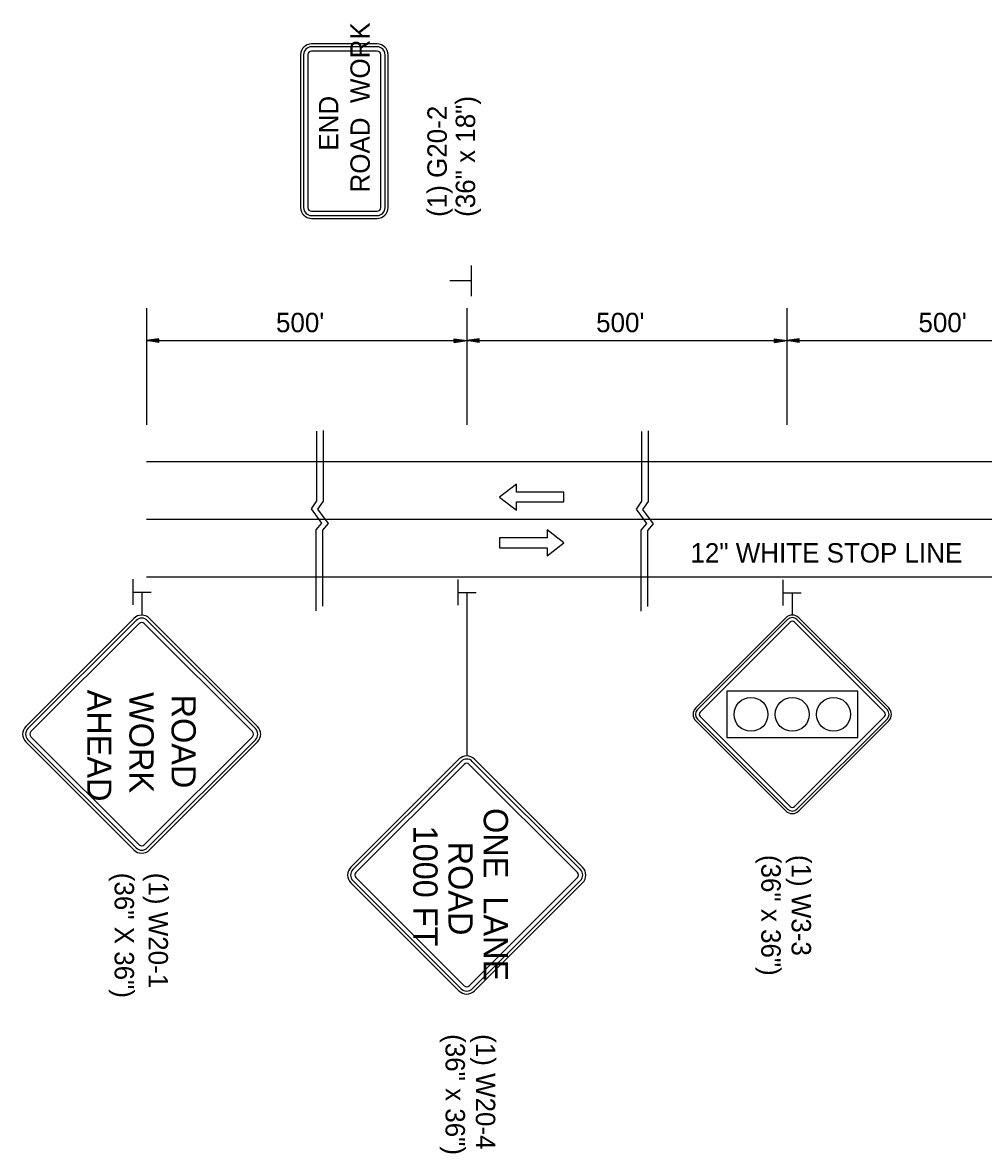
# Model space of a CAD drawing. Extents: x 1926586 to 1930787, y 596452 to 599566.
# Drawn here: x 1927871.2 to 1928168, y 599216.2 to 599565.7 of the extents above; entities that cross this region are included whole.
import ezdxf

# ---------------------------------------------------------------- set-up
doc = ezdxf.new("R2010")
doc.units = 0
for name, color, linetype in [('Default', 7, 'Continuous'), ('P_TC_Signs_Permanent', 7, 'Continuous'), ('P_TC_Signs_Temporary', 7, 'Continuous'), ('R_Border', 7, 'Continuous'), ('R_Striping', 7, 'Continuous')]:
    doc.layers.add(name, color=color, linetype=linetype)

msp = doc.modelspace()

# ---------------------------------------------------------------- linework, layer by layer
at = {"layer": 'Default'}
for p, q in [((1928009.74, 599490.57), (1928009.74, 599481.08)), ((1928009.6, 599485.85), (1928003.12, 599485.85)), ((1927909.48, 599477.43), (1927909.48, 599441.4)), ((1928008.38, 599477.43), (1928008.38, 599441.4)), ((1928107.28, 599477.43), (1928107.28, 599441.4)), ((1927913.32, 599467.97), (1927909.48, 599467.39)), ((1927909.48, 599467.39), (1928008.38, 599467.39)), ((1927913.32, 599466.82), (1927909.48, 599467.39)), ((1927913.32, 599467.87), (1927910.12, 599467.39)), ((1927913.32, 599466.91), (1927910.12, 599467.39)), ((1927913.32, 599467.78), (1927910.78, 599467.39)), ((1927913.32, 599467.01), (1927910.78, 599467.39)), ((1927913.32, 599467.68), (1927911.42, 599467.39)), ((1927913.32, 599467.11), (1927911.42, 599467.39)), ((1927913.32, 599467.58), (1927912.07, 599467.39)), ((1927913.32, 599467.21), (1927912.07, 599467.39)), ((1927913.32, 599467.48), (1927912.71, 599467.39)), ((1927913.32, 599467.3), (1927912.71, 599467.39)), ((1927913.32, 599466.82), (1927913.32, 599467.97)), ((1928004.54, 599467.97), (1928008.38, 599467.39)), ((1928004.54, 599466.82), (1928004.54, 599467.97)), ((1928004.54, 599467.87), (1928007.74, 599467.39)), ((1928004.54, 599467.78), (1928007.08, 599467.39)), ((1928004.54, 599467.68), (1928006.44, 599467.39)), ((1928004.54, 599467.58), (1928005.79, 599467.39)), ((1928004.54, 599467.48), (1928005.15, 599467.39)), ((1928004.54, 599466.82), (1928008.38, 599467.39)), ((1928004.54, 599467.21), (1928005.79, 599467.39)), ((1928004.54, 599467.01), (1928007.08, 599467.39)), ((1928004.54, 599466.91), (1928007.74, 599467.39)), ((1928004.54, 599467.11), (1928006.44, 599467.39)), ((1928004.54, 599467.3), (1928005.15, 599467.39)), ((1928012.22, 599467.97), (1928008.38, 599467.39)), ((1928008.38, 599467.39), (1928107.28, 599467.39)), ((1928012.22, 599466.82), (1928008.38, 599467.39)), ((1928012.22, 599467.87), (1928009.02, 599467.39)), ((1928012.22, 599466.91), (1928009.02, 599467.39)), ((1928012.22, 599467.78), (1928009.68, 599467.39)), ((1928012.22, 599467.01), (1928009.68, 599467.39)), ((1928012.22, 599467.68), (1928010.32, 599467.39)), ((1928012.22, 599467.11), (1928010.32, 599467.39)), ((1928012.22, 599467.58), (1928010.97, 599467.39)), ((1928012.22, 599467.21), (1928010.97, 599467.39)), ((1928012.22, 599467.48), (1928011.61, 599467.39)), ((1928012.22, 599467.3), (1928011.61, 599467.39)), ((1928012.22, 599466.82), (1928012.22, 599467.97)), ((1928103.44, 599467.97), (1928107.28, 599467.39)), ((1928103.44, 599466.82), (1928103.44, 599467.97)), ((1928103.44, 599467.87), (1928106.64, 599467.39)), ((1928103.44, 599467.78), (1928105.98, 599467.39)), ((1928103.44, 599467.68), (1928105.34, 599467.39)), ((1928103.44, 599467.58), (1928104.69, 599467.39)), ((1928103.44, 599467.48), (1928104.05, 599467.39)), ((1928103.44, 599466.82), (1928107.28, 599467.39)), ((1928103.44, 599467.21), (1928104.69, 599467.39)), ((1928103.44, 599467.01), (1928105.98, 599467.39)), ((1928103.44, 599466.91), (1928106.64, 599467.39)), ((1928103.44, 599467.11), (1928105.34, 599467.39)), ((1928103.44, 599467.3), (1928104.05, 599467.39)), ((1928111.12, 599467.97), (1928107.28, 599467.39)), ((1928107.28, 599467.39), (1928208.41, 599467.39)), ((1928111.12, 599466.82), (1928107.28, 599467.39)), ((1928111.12, 599467.87), (1928107.92, 599467.39)), ((1928111.12, 599466.91), (1928107.92, 599467.39)), ((1928111.12, 599467.78), (1928108.58, 599467.39)), ((1928111.12, 599467.01), (1928108.58, 599467.39)), ((1928111.12, 599467.68), (1928109.22, 599467.39)), ((1928111.12, 599467.11), (1928109.22, 599467.39)), ((1928111.12, 599467.58), (1928109.87, 599467.39)), ((1928111.12, 599467.21), (1928109.87, 599467.39)), ((1928111.12, 599467.48), (1928110.51, 599467.39)), ((1928111.12, 599467.3), (1928110.51, 599467.39)), ((1928111.12, 599466.82), (1928111.12, 599467.97)), ((1927909.48, 599429.98), (1928798.33, 599429.98)), ((1927909.48, 599412.19), (1928798.33, 599412.19)), ((1927905.3, 599385.7), (1927905.3, 599393.7)), ((1927909.48, 599394.4), (1928798.33, 599394.4)), ((1928005.7, 599385.6), (1928005.7, 599393.6)), ((1928106.1, 599385.5), (1928106.1, 599393.5)), ((1927905.42, 599389.68), (1927910.88, 599389.68)), ((1928005.82, 599389.58), (1928011.28, 599389.58)), ((1928106.22, 599389.48), (1928111.68, 599389.48))]:
    msp.add_line(p, q, dxfattribs=at)
for points in [[(1927961.95, 599439.36), (1927961.95, 599417.84), (1927960.29, 599415.37), (1927963.52, 599410.94), (1927961.82, 599408.9), (1927961.82, 599383.87)], [(1927963.99, 599439.56), (1927963.99, 599417.76), (1927962.33, 599415.28), (1927965.57, 599410.86), (1927963.86, 599408.81), (1927963.86, 599385.31)], [(1928062.35, 599439.26), (1928062.35, 599417.74), (1928060.69, 599415.27), (1928063.92, 599410.84), (1928062.22, 599408.79), (1928062.22, 599383.77)], [(1928064.39, 599439.46), (1928064.39, 599417.66), (1928062.73, 599415.18), (1928065.97, 599410.75), (1928064.26, 599408.71), (1928064.26, 599385.21)]]:
    msp.add_lwpolyline(points, dxfattribs=at)
at = {"layer": 'P_TC_Signs_Permanent'}
for p, q in [((1928079.12, 599353.87), (1928106.96, 599381.71)), ((1928110.94, 599381.71), (1928138.78, 599353.87)), ((1928079.65, 599353.34), (1928107.49, 599381.18)), ((1928108.29, 599380.39), (1928080.45, 599352.55)), ((1928137.46, 599352.55), (1928109.61, 599380.39)), ((1928110.41, 599381.18), (1928138.25, 599353.34)), ((1928107.49, 599322.58), (1928079.65, 599350.43)), ((1928080.45, 599351.22), (1928108.29, 599323.38)), ((1928109.61, 599323.38), (1928137.46, 599351.22)), ((1928138.25, 599350.43), (1928110.41, 599322.58)), ((1928106.96, 599322.05), (1928079.12, 599349.9)), ((1928138.78, 599349.9), (1928110.94, 599322.05))]:
    msp.add_line(p, q, dxfattribs=at)
msp.add_lwpolyline([(1928088.7, 599359.01), (1928088.7, 599344.76), (1928129.2, 599344.76), (1928129.2, 599359.01)], close=True, dxfattribs=at)
for centre in [(1928096.2, 599351.88), (1928108.95, 599351.88), (1928121.7, 599351.88)]:
    msp.add_circle(centre, 5.25, dxfattribs=at)
for centre, radius, start, end in [((1928108.95, 599379.73), 2.81, 45, 135), ((1928108.95, 599379.73), 2.06, 45, 135), ((1928108.95, 599379.73), 0.938, 45, 135), ((1928081.11, 599351.88), 2.81, 135, 225), ((1928136.79, 599351.88), 2.81, 315, 45), ((1928081.11, 599351.88), 2.06, 135, 225), ((1928081.11, 599351.88), 0.938, 135, 225), ((1928136.79, 599351.88), 0.938, 315, 45), ((1928136.79, 599351.88), 2.06, 315, 45), ((1928108.95, 599324.04), 2.06, 225, 315), ((1928108.95, 599324.04), 0.938, 225, 315), ((1928108.95, 599324.04), 2.81, 225, 315)]:
    msp.add_arc(centre, radius, start, end, dxfattribs=at)
at = {"layer": 'P_TC_Signs_Temporary'}
for p, q in [((1927980.7, 599559.13), (1927960.45, 599559.13)), ((1927980.7, 599558.19), (1927960.45, 599558.19)), ((1927980.7, 599556.88), (1927960.45, 599556.88)), ((1927957.07, 599555.75), (1927957.07, 599508.5)), ((1927958.01, 599555.75), (1927958.01, 599508.5)), ((1927959.32, 599555.75), (1927959.32, 599508.5)), ((1927981.82, 599508.5), (1927981.82, 599555.75)), ((1927983.14, 599508.5), (1927983.14, 599555.75)), ((1927984.07, 599508.5), (1927984.07, 599555.75)), ((1927960.45, 599507.38), (1927980.7, 599507.38)), ((1927960.45, 599506.06), (1927980.7, 599506.06)), ((1927960.45, 599505.13), (1927980.7, 599505.13)), ((1927872.18, 599348.14), (1927905.59, 599381.55)), ((1927872.84, 599347.48), (1927906.25, 599380.89)), ((1927873.77, 599346.55), (1927907.18, 599379.96)), ((1927908.77, 599379.96), (1927942.18, 599346.55)), ((1927909.7, 599380.89), (1927943.11, 599347.48)), ((1927910.36, 599381.55), (1927943.78, 599348.14)), ((1927905.59, 599309.96), (1927872.18, 599343.37)), ((1927906.25, 599310.62), (1927872.84, 599344.03)), ((1927907.18, 599311.55), (1927873.77, 599344.96)), ((1927942.18, 599344.96), (1927908.77, 599311.55)), ((1927943.11, 599344.03), (1927909.7, 599310.62)), ((1927943.78, 599343.37), (1927910.36, 599309.96)), ((1927972.58, 599304.6), (1928005.99, 599338.01)), ((1927973.24, 599303.94), (1928006.65, 599337.35)), ((1927974.17, 599303.01), (1928007.58, 599336.42)), ((1928009.17, 599336.42), (1928042.58, 599303.01)), ((1928010.1, 599337.35), (1928043.51, 599303.94)), ((1928010.76, 599338.01), (1928044.18, 599304.6)), ((1928007.58, 599268.01), (1927974.17, 599301.42)), ((1928042.58, 599301.42), (1928009.17, 599268.01)), ((1928005.99, 599266.42), (1927972.58, 599299.83)), ((1928006.65, 599267.08), (1927973.24, 599300.49)), ((1928043.51, 599300.49), (1928010.1, 599267.08)), ((1928044.18, 599299.83), (1928010.76, 599266.42))]:
    msp.add_line(p, q, dxfattribs=at)
for centre, radius, start, end in [((1927960.45, 599555.75), 3.37, 90, 180), ((1927960.45, 599555.75), 2.44, 90, 180), ((1927960.45, 599555.75), 1.13, 90, 180), ((1927980.7, 599555.75), 3.37, 360, 90), ((1927980.7, 599555.75), 2.44, 360, 90), ((1927980.7, 599555.75), 1.13, 360, 90), ((1927960.45, 599508.5), 3.37, 180, 270), ((1927960.45, 599508.5), 2.44, 180, 270), ((1927960.45, 599508.5), 1.13, 180, 270), ((1927980.7, 599508.5), 2.44, 270, 360), ((1927980.7, 599508.5), 1.13, 270, 360), ((1927980.7, 599508.5), 3.37, 270, 360), ((1927907.98, 599379.16), 3.37, 45, 135), ((1927907.98, 599379.16), 2.44, 45, 135), ((1927907.98, 599379.16), 1.12, 45, 135), ((1927874.57, 599345.75), 3.37, 135, 225), ((1927874.57, 599345.75), 2.44, 135, 225), ((1927941.39, 599345.75), 2.44, 315, 45), ((1927941.39, 599345.75), 3.37, 315, 45), ((1927874.57, 599345.75), 1.13, 135, 225), ((1927941.39, 599345.75), 1.13, 315, 45), ((1928008.38, 599335.63), 3.38, 45, 135), ((1928008.38, 599335.63), 2.44, 45, 135), ((1928008.38, 599335.63), 1.13, 45, 135), ((1927907.98, 599312.34), 3.37, 225, 315), ((1927907.98, 599312.34), 2.44, 225, 315), ((1927907.98, 599312.34), 1.12, 225, 315), ((1927974.97, 599302.22), 3.38, 135, 225), ((1927974.97, 599302.22), 2.44, 135, 225), ((1927974.97, 599302.22), 1.13, 135, 225), ((1928041.79, 599302.22), 1.13, 315, 45), ((1928041.79, 599302.22), 2.44, 315, 45), ((1928041.79, 599302.22), 3.38, 315, 45), ((1928008.38, 599268.8), 3.38, 225, 315), ((1928008.38, 599268.8), 2.44, 225, 315), ((1928008.38, 599268.8), 1.13, 225, 315)]:
    msp.add_arc(centre, radius, start, end, dxfattribs=at)
at = {"layer": 'R_Border'}
for p, q in [((1927907.98, 599389.68), (1927907.98, 599382.54)), ((1928008.38, 599389.58), (1928008.38, 599339)), ((1928108.95, 599389.48), (1928108.95, 599382.54))]:
    msp.add_line(p, q, dxfattribs=at)
at = {"layer": 'R_Striping'}
for points in [[(1928023.72, 599423.03), (1928018.53, 599419.03), (1928023.72, 599415.03), (1928023.72, 599417.53), (1928038.43, 599417.53), (1928038.43, 599420.53), (1928023.72, 599420.53)], [(1928033.24, 599400.89), (1928038.43, 599404.89), (1928033.24, 599408.89), (1928033.24, 599406.39), (1928018.53, 599406.39), (1928018.53, 599403.39), (1928033.24, 599403.39)]]:
    msp.add_lwpolyline(points, close=True, dxfattribs=at)

# ---------------------------------------------------------------- texts
at = {"layer": 'Default'}
for s, height, p in [("500'", 6, (1927949.46, 599469.99)), ("500'", 6, (1928048.36, 599469.99)), ("500'", 6, (1928147.94, 599469.99)), ('12" WHITE STOP LINE', 5.9996, (1928077.49, 599398.79))]:
    msp.add_text(s, height=height, rotation=360, dxfattribs=at).set_placement(p)
at = {"layer": 'P_TC_Signs_Temporary'}
for s, height, rotation, p in [('ROAD  WORK', 6, 90, (1927978.45, 599513.17)), ('END', 6, 90, (1927968.7, 599526.1)), (' AHEAD ', 7.5, 270, (1927891.14, 599362.29)), ('WORK', 7.5, 270, (1927904.17, 599358.74)), (' ROAD ', 7.5, 270, (1927917.19, 599360.77)), ('ONE  LANE', 7.5, 270, (1928013.63, 599322.92)), ('1000 FT', 7.5, 270, (1927991.88, 599317.51)), ('ROAD', 7.5, 270, (1928002.75, 599312.52))]:
    msp.add_text(s, height=height, rotation=rotation, dxfattribs=at).set_placement(p)
at = {"layer": 'R_Border'}
for s, height, rotation, p in [('(36" x 18")', 5.9996, 90, (1928010.98, 599505.64)), ('(1) G20-2', 6, 90, (1928002.23, 599505.64)), ('(36" x 36")', 5.9996, 270, (1928099.38, 599308.44)), ('(1) W3-3', 6, 270, (1928108.74, 599308.44)), ('(36" X 36")', 6, 270, (1927899.61, 599302.92)), ('(1) W20-1', 6, 270, (1927910.09, 599302.92)), ('(36" x 36")', 5.9996, 270, (1928001.84, 599253.04)), ('(1) W20-4', 6, 270, (1928011.2, 599253.04))]:
    msp.add_text(s, height=height, rotation=rotation, dxfattribs=at).set_placement(p)

doc.saveas('drawing.dxf')
